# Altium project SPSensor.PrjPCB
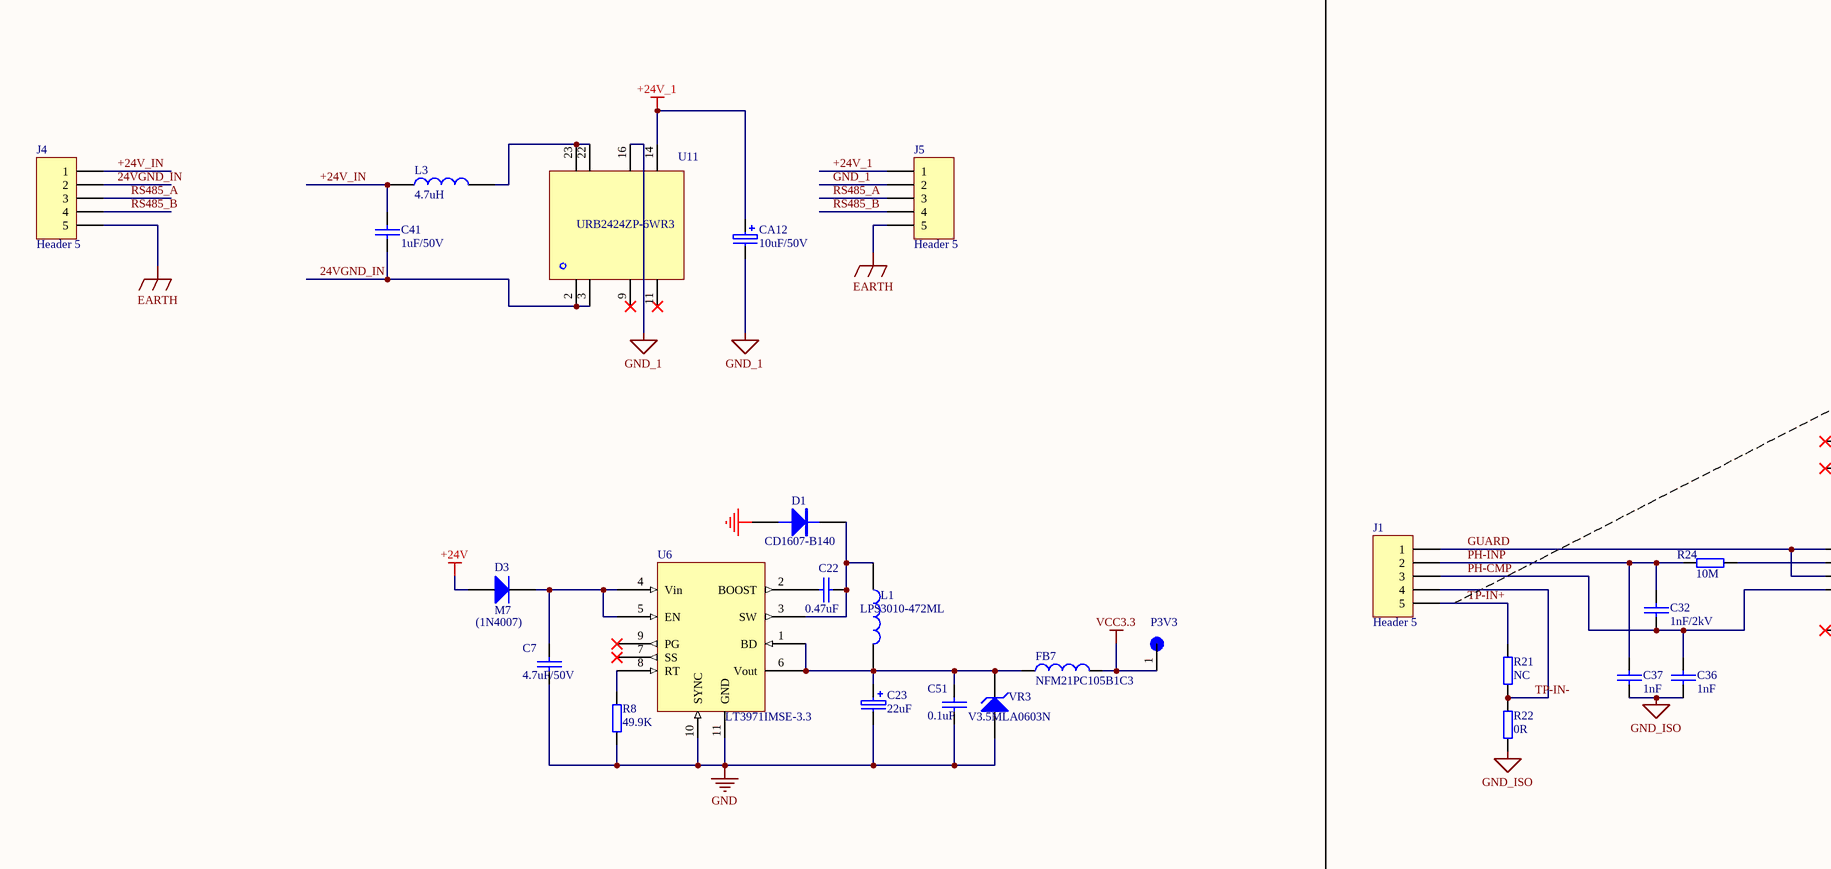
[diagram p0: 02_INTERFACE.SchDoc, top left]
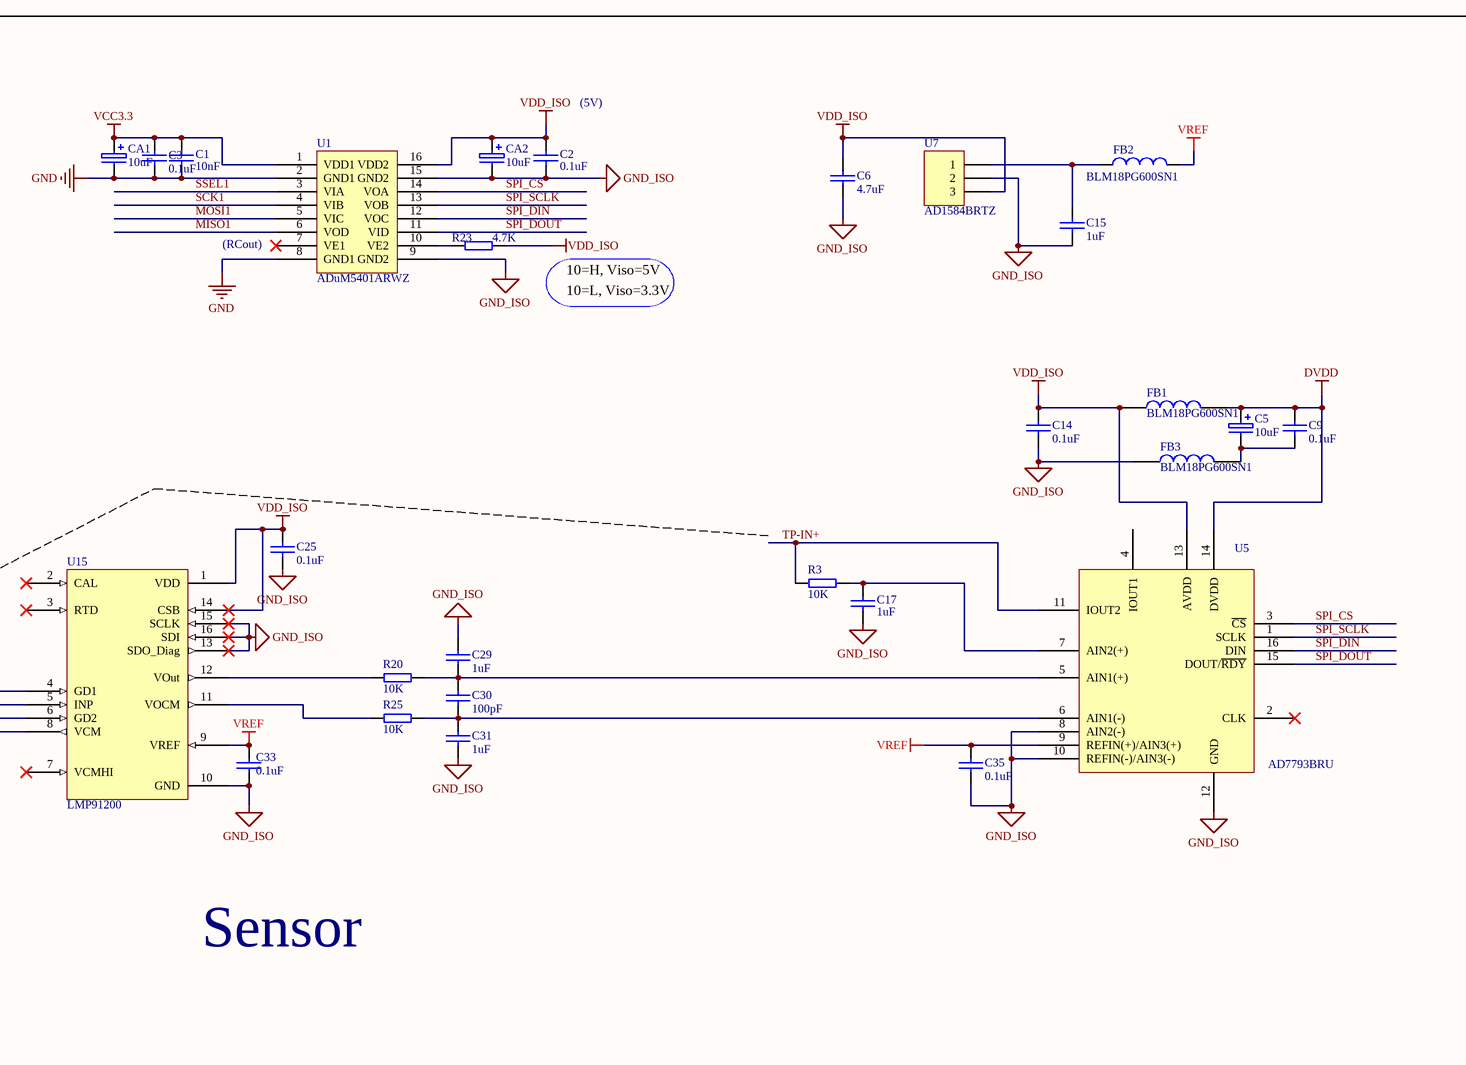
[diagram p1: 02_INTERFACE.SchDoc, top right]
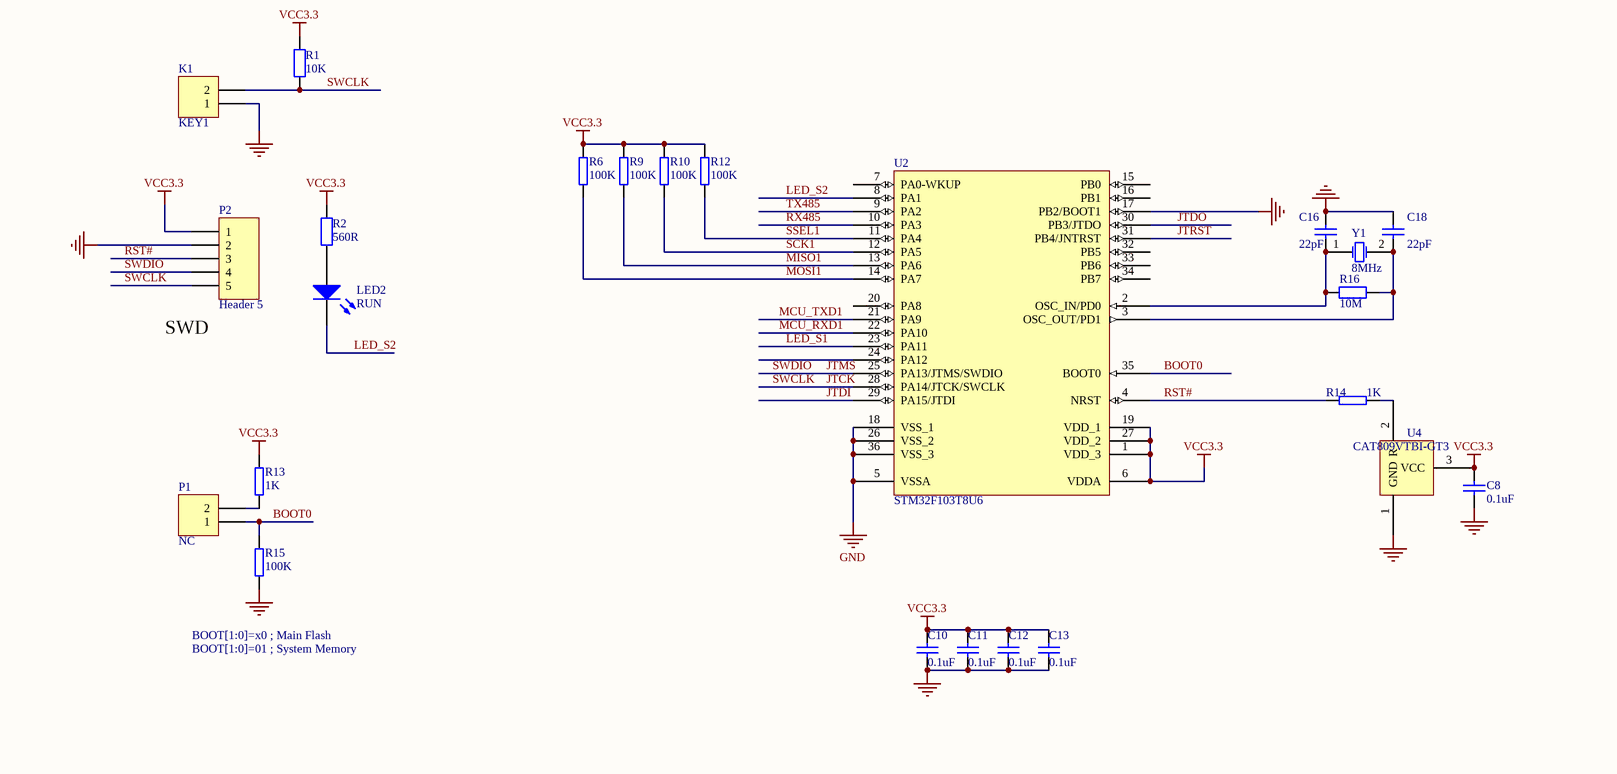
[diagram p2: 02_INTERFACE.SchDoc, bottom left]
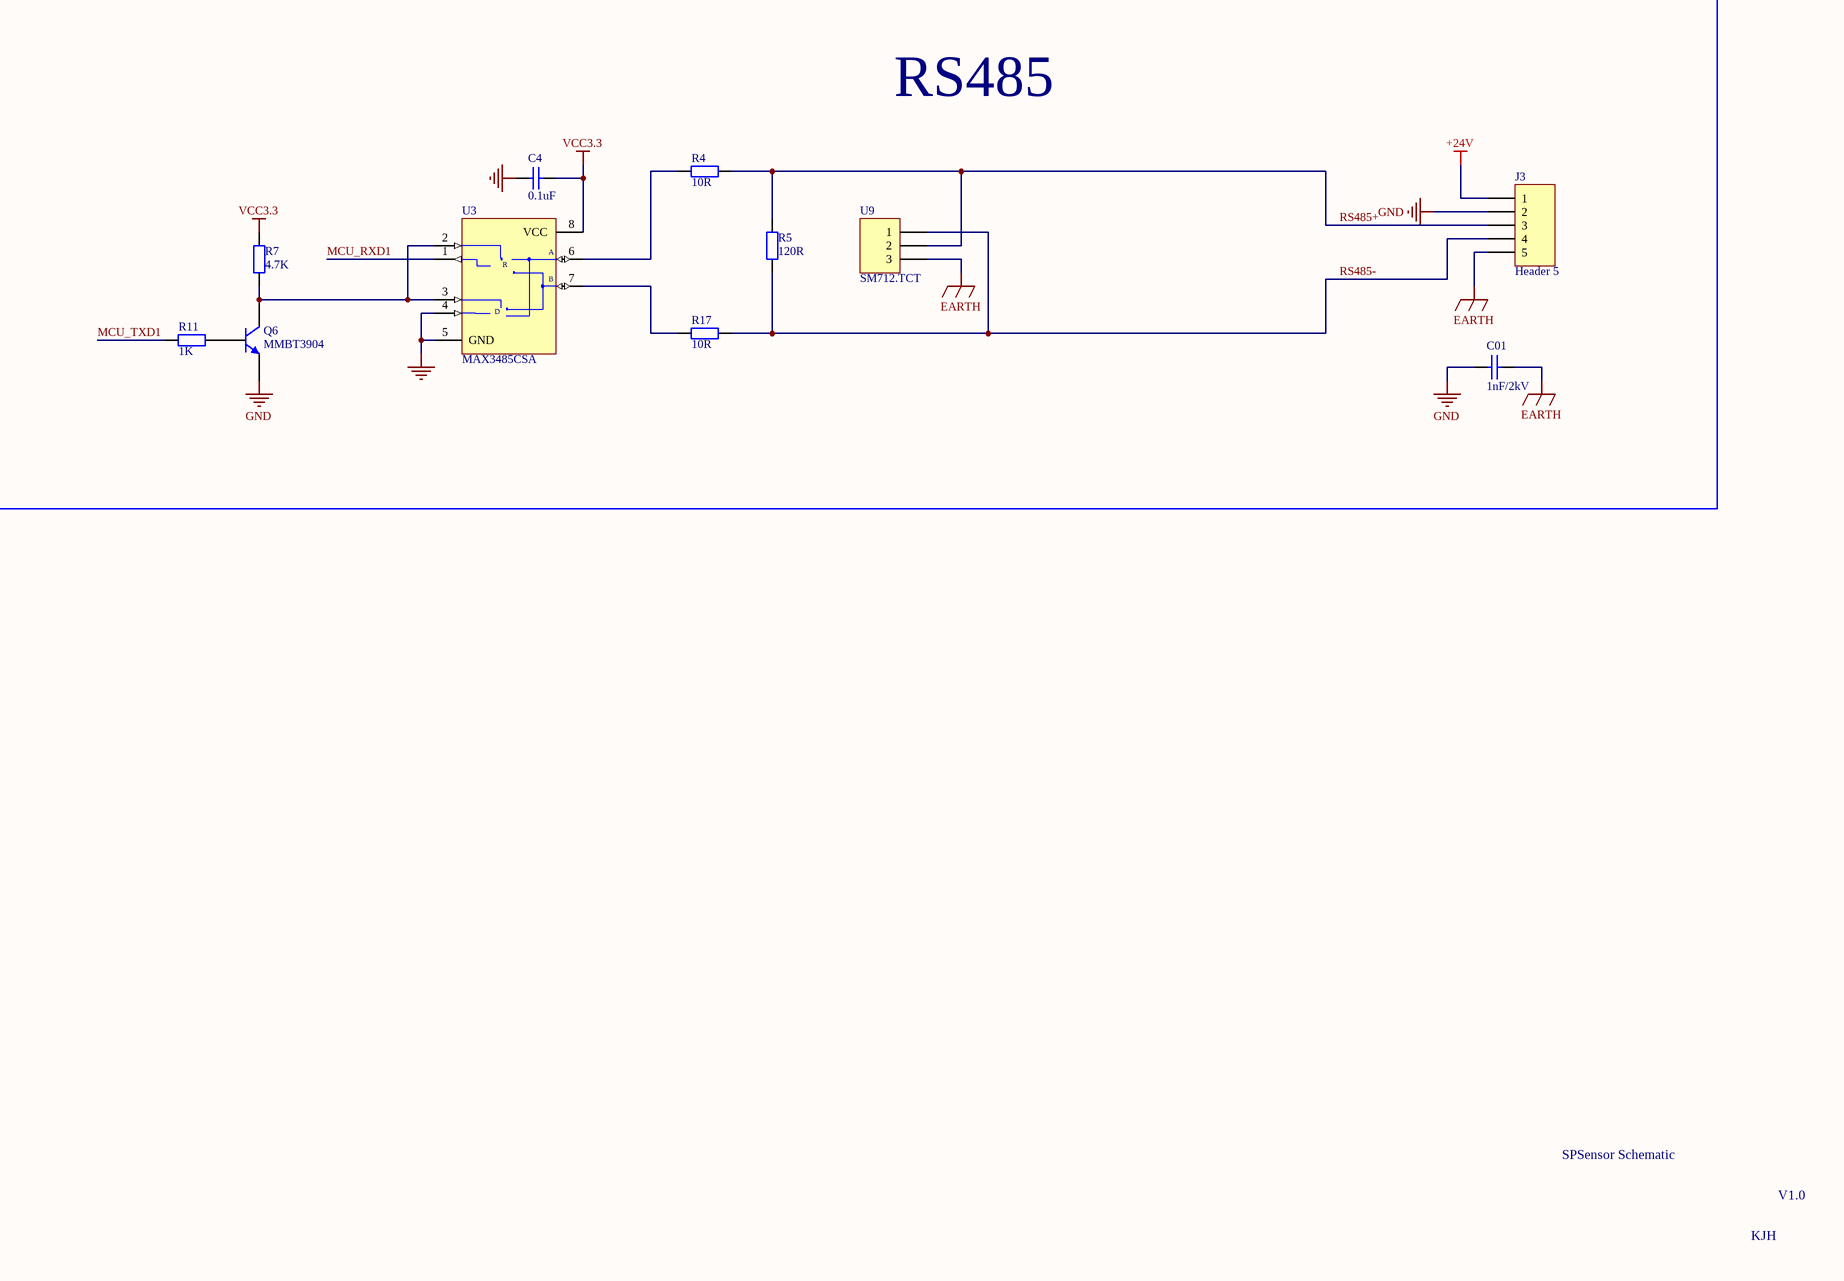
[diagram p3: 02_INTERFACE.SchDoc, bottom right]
1 sheet, 88 parts. Net scope: global (net labels, ports and power ports of the same name join across sheets).
Board file: SPSensor V0.3.PcbDoc

## Sheet 02_INTERFACE.SchDoc
size D; SheetNumber: 0; SheetTotal: 0

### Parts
C1  10nF  [SM0603]
C01  1nF/2kV  [SM1206]
C2  0.1uF  [SM0603]
C3  0.1uF  [SM0603]
C4  0.1uF  [SM0603]
C5  10uF  [SM1206]
C6  4.7uF  [SM0603]
C7  4.7uF/50V  [SM1206]
C8  0.1uF  [SM0603]
C9  0.1uF  [SM0603]
C10  0.1uF  [SM0603]
C11  0.1uF  [SM0603]
C12  0.1uF  [SM0603]
C13  0.1uF  [SM0603]
C14  0.1uF  [SM0603]
C15  1uF  [SM0603]
C16  22pF  [SM0603]
C17  1uF  [SM0603]
C18  22pF  [SM0603]
C22  0.47uF  [SM0603]
C23  22uF  [SM1206]
C25  0.1uF  [SM0603]
C29  1uF  [SM0603]
C30  100pF  [SM0603]
C31  1uF  [SM0603]
C32  1nF/2kV  [SM0805]
C33  0.1uF  [SM0603]
C35  0.1uF  [SM0603]
C36  1nF  [0805A]
C37  1nF  [0805A]
C41  1uF/50V  [SM0805]
C51  0.1uF  [SM0603]
CA1  10uF  [SM1206]
CA2  10uF  [SM1206]
CA12  10uF/50V  [SM1206]
D1  CD1607-B140  [1206D]
D3  M7  [1206D]
FB1  BLM18PG600SN1  [SM0603]
FB2  BLM18PG600SN1  [SM0603]
FB3  BLM18PG600SN1  [SM0603]
FB7  NFM21PC105B1C3  [NFM21PC105]
J1  Header 5  [CON1x5-3.5mm]
J3  Header 5  [HDR1X5]
J4  Header 5  [HDR1X5]
J5  Header 5  [HDR1X5]
K1  KEY1  [SM0603]
L1  LPS3010-472ML  [LPS3010]
L3  4.7uH  [LPS3010]
LED2  RUN  [SM0805]
P1  NC  [SM0603]
P2  Header 5  [HDR1X5]
P3V3  TestPoint  [test point]  (value not drawn)
Q6  MMBT3904  [SOT23_N]
R1  10K  [SM0603]
R2  560R  [SM0603]
R3  10K  [SM0603]
R4  10R  [SM0603]
R5  120R  [SM0603]
R6  100K  [SM0603]
R7  4.7K  [SM0603]
R8  49.9K  [SM0603]
R9  100K  [SM0603]
R10  100K  [SM0603]
R11  1K  [SM0603]
R12  100K  [SM0603]
R13  1K  [SM0603]
R14  1K  [SM0603]
R15  100K  [SM0603]
R16  10M  [SM0603]
R17  10R  [SM0603]
R20  10K  [SM0603]
R21  NC  [SM0603]
R22  0R  [SM0603]
R23  4.7K  [SM0603]
R24  10M  [SM0603]
R25  10K  [SM0603]
U1  ADuM5401ARWZ  [ADUM1401]
U2  STM32F103T8U6  [VFQN36_V]
U3  MAX3485CSA  [NSO8_N]
U4  CAT809VTBI-GT3  [SOT-23]
U5  AD7793BRU  [AD7793]
U6  LT3971IMSE-3.3  [LT3971]
U7  AD1584BRTZ  [SOT-23]
U9  SM712.TCT  [SOT-23]
U11  URB2424ZP-6WR3  [URB2424ZP-6WR3]
U15  LMP91200  [LMP91200]
VR3  V3.5MLA0603N  [SM0603]
Y1  8MHz  [CY5.4X4.6]

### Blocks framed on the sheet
Sensor: C1-C3 C5 C6 C9 C14 C15 C17 C25 C29-C33 C35-C37 CA1 CA2 FB1-FB3 J1 R3 R20-R25 U1 U5 U7 U15
RS485: C01 C4 J3 Q6 R4 R5 R7 R11 R17 U3 U9

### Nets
+24V: D3.1(A) J3.1
+24V_1: CA12.1 J5.1 U11.14
DVDD: C5.1 C9.1 FB1.2 U5.14(DVDD)
EARTH: C01.2 J3.5 J4.5 J5.5 U9.3
GND: C01.1 C1.2 C3.1 C4.2 C7.2 C8.2 C10.2 C11.2 C12.2 C13.2 C16.2 C18.2 C23.2 C51.2 CA1.2 D1.1(A) J3.2 K1.1 P2.2 Q6.2(E) R8.1 R15.1 U1.2(GND1) U1.8(GND1) U2.5(VSSA) U2.17(PB2/BOOT1) U2.18(VSS_1) U2.26(VSS_2) U2.36(VSS_3) U3.4(DI) U3.5(GND) U4.1(GND) U6.10(SYNC) U6.11(GND) VR3.1(A)
GND_1: CA12.2 J5.2 U11.16
GND_ISO: C2.2 C6.2 C14.2 C15.2 C17.2 C25.2 C29.1 C31.2 C33.2 C35.2 C36.2 C37.2 CA2.2 FB3.1 R22.1 U1.9(GND2) U1.15(GND2) U5.8(AIN2(-)) U5.10(REFIN(-)/AIN3(-)) U5.12(GND) U7.2 U15.10(GND) U15.13(SDO_Diag) U15.15(SCLK) U15.16(SDI)
VCC3.3: C1.1 C3.2 C4.1 C8.1 C10.1 C11.1 C12.1 C13.1 CA1.1 FB7.2 P2.1 P3V3.1 R1.1 R2.1 R6.1 R7.2 R9.1 R10.1 R12.1 R13.1 U1.1(VDD1) U2.1(VDD_3) U2.6(VDDA) U2.19(VDD_1) U2.27(VDD_2) U3.8(VCC) U4.3(VCC)
VDD_ISO: C2.1 C6.1 C14.1 C25.1 CA2.1 FB1.1 R23.2 U1.16(VDD2) U5.13(AVDD) U7.3 U15.1(VDD) U15.14(CSB)
VREF: C33.1 C35.1 FB2.2 U5.9(REFIN(+)/AIN3(+)) U15.9(VREF)
24VGND_IN: C41.2 J4.2 U11.2 U11.3
+24V_IN: C41.1 J4.1 L3.1
BOOT0: P1.1 R15.2 U2.35(BOOT0)
GUARD: J1.1 U15.4(GD1) U15.6(GD2)
JTCK: K1.2 P2.5 R1.2 U2.28(PA14/JTCK/SWCLK)  [also labelled SWCLK]
JTDI: U2.29(PA15/JTDI)
JTDO: U2.30(PB3/JTDO)
JTMS: P2.4 U2.25(PA13/JTMS/SWDIO)  [also labelled SWDIO]
JTRST: U2.31(PB4/JNTRST)
LED_S1: U2.23(PA11)
LED_S2: LED2.2(K) U2.8(PA1)
MCU_RXD1: U2.22(PA10) U3.1(RO)
MCU_TXD1: R11.1 U2.21(PA9)
MISO1: R9.2 U1.6(VOD) U2.13(PA6)
MOSI1: R6.2 U1.5(VIC) U2.14(PA7)
PH-CMP: C32.2 C36.1 J1.3 U15.8(VCM)
PH-INP: C32.1 C37.1 J1.2 R24.1
RS485+: J3.3 R4.1 R5.2 U9.2
RS485-: J3.4 R5.1 R17.1 U9.1
RS485_A: J4.3 J5.3
RS485_B: J4.4 J5.4
RST#: P2.3 R14.2 U2.4(NRST)
RX485: U2.10(PA3)
SCK1: R10.2 U1.4(VIB) U2.12(PA5)
SPI_CS: U1.14(VOA) U5.3(~{CS})
SPI_DIN: U1.12(VOC) U5.16(DIN)
SPI_DOUT: U1.11(VID) U5.15(DOUT/~{RDY})
SPI_SCLK: U1.13(VOB) U5.1(SCLK)
SSEL1: R12.2 U1.3(VIA) U2.11(PA4)
TP-IN+: J1.5 R3.1 R21.2 U5.11(IOUT2)
TP-IN-: J1.4 R21.1 R22.2
TX485: U2.9(PA2)
NetC5_2: C5.2 C9.2 FB3.2
NetC7_1: C7.1 D3.2(K) U6.4(Vin) U6.5(EN)
NetC15_1: C15.1 FB2.1 U7.1
NetC16_1: C16.1 R16.1 U2.2(OSC_IN/PD0) Y1.1(OSC1)
NetC17_1: C17.1 R3.2 U5.7(AIN2(+))
NetC18_1: C18.1 R16.2 U2.3(OSC_OUT/PD1) Y1.2(OSC2)
NetC22_1: C22.1 U6.2(BOOST)
NetC22_2: C22.2 D1.2(K) L1.1 U6.3(SW)
NetC23_1: C23.1 C51.1 FB7.1 L1.2 U6.1(BD) U6.6(Vout) VR3.2(K)
NetC29_2: C29.2 C30.1 R20.2 U5.5(AIN1(+))
NetC30_2: C30.2 C31.1 R25.2 U5.6(AIN1(-))
NetL3_2: L3.2 U11.22 U11.23
NetLED2_1: LED2.1(A) R2.2
NetP1_2: P1.2 R13.2
NetQ6_1: Q6.1(B) R11.2
NetQ6_3: Q6.3(C) R7.1 U3.2(~{RE}) U3.3(DE)
NetR4_2: R4.2 U3.6(A)
NetR8_2: R8.2 U6.8(RT)
NetR14_1: R14.1 U4.2(R)
NetR17_2: R17.2 U3.7(B)
NetR20_1: R20.1 U15.12(VOut)
NetR23_1: R23.1 U1.10(VE2)
NetR24_2: R24.2 U15.5(INP)
NetR25_1: R25.1 U15.11(VOCM)

Not connected (* = marked no-connect by the designer): U1 7(VE1)*; U2 7(PA0-WKUP) 15(PB0) 16(PB1) 20(PA8) 24(PA12) 32(PB5) 33(PB6) 34(PB7); U5 2(CLK)* 4(IOUT1); U6 7(SS)* 9(PG)*; U11 9* 11*; U15 2(CAL)* 3(RTD)* 7(VCMHI)*

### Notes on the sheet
- (near C2) (5V)
- (near U1) (RCout)
- 10=H, Viso=5V
- 10=L, Viso=3.3V
- (1N4007)
- (near P2) SWD
- BOOT[1:0]=x0 ; Main Flash
- BOOT[1:0]=01 ; System Memory
- SPSensor Schematic
- KJH
- V1.0

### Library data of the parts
C1 C01 C6 C7 C9 C14 C15 C22 C25 C29-C33 C35-C37 C41 C51 = CAP: Capacitor
C2 C3 = C: 电容
C4 C8 = Cap: Capacitor, X7R Ceramic
C5 = C: 极性电容
C10-C13 = Cap: Capacitor
C16 C18 = Cap: Capacitor; Value: 0.1uF
C17 = CA: 电容
C23 = CAPE: 极性电容
CA1 CA2 CA12 = CAPE: Capacitor
D1 = DIODE
D3 = Diode 1N4007: 1 Amp General Purpose Rectifier
FB1 FB3 L1 L3 = INDUCTOR
FB2 FB7 = Inductor: Code_IEC: 1005; Value: 10mH
J1 J3-J5 P2 = Header 5: Header, 5-Pin
K1 = Header 2: Header, 2-Pin
LED2 = LED0: Typical INFRARED GaAs LED
P1 = He: Header, 2-Pin, 2.54mm, 排针
Q6 = MMBT3904: NPN Switching Transistor
R1 R2 R4 R5 R7 R16 R17 = Res2: Resistor; Value: 1K
R3 R6 R9 R10 R12 R20-R22 R25 = RE: 电阻
R8 R13-R15 R23 = R: 电阻
R11 = Res2: Resistor
R24 = RES: 电阻
U1 = ADUM1401: 1Mbps Data Rate, 100ns Propagation delay
U2 = STM32F103T8U6: STM32 ARM-based 32-bit MCU with 64 Kbytes Flash, 36-pin VFQFPN, Industrial Temperature
U3 = MAX485CSA: Low-Power, Slew-Rate-Limited RS-485/RS-422 Transceiver
U4 = CA: Onsemi RESET
U5 = AD7793
U6 = LT3971
U7 = Header 3: 4.096V reference
U9 = Header 3: Asymmerical TVS Diode for RS485
VR3 = D Zener: Zener Diode
Y1 = XTAL: Crystal Oscillator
